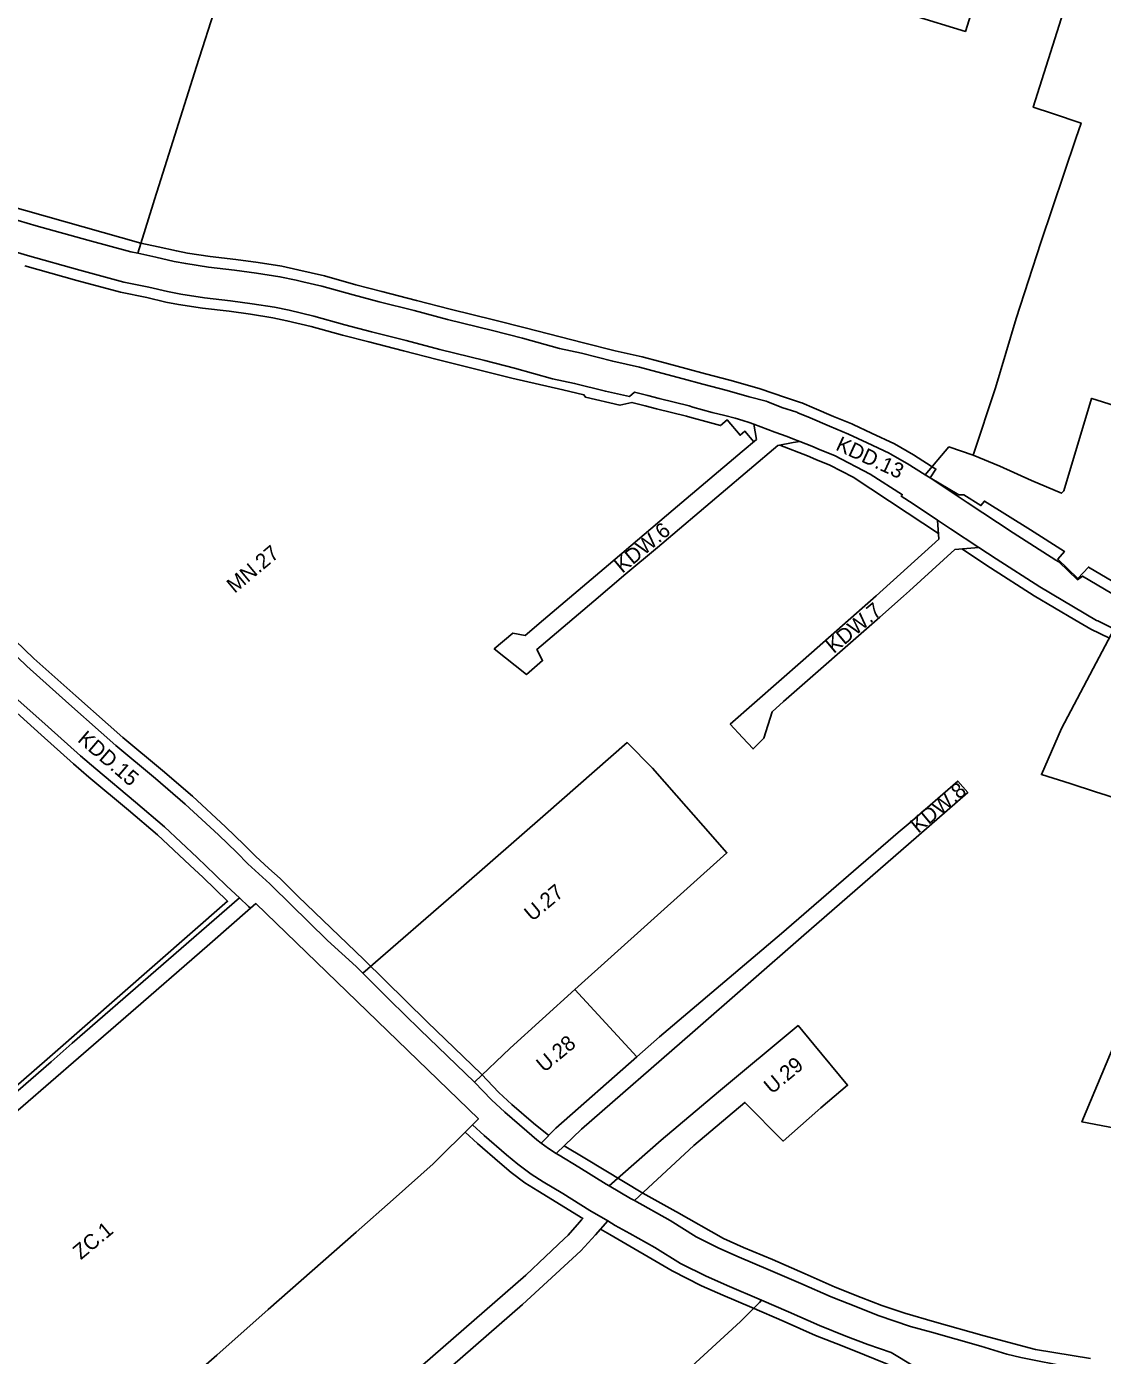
# Model space of a CAD drawing. Extents: x 7418616 to 7420822, y 5550745 to 5553106.
# Drawn here: x 7419553.4 to 7419907.9, y 5551619.2 to 5552057.3 of the extents above; entities that cross this region are included whole.
import ezdxf

# ---------------------------------------------------------------- set-up
doc = ezdxf.new("R2010")
doc.units = 0
for name, color, linetype in [('linie rozgraniczające', 7, 'Continuous'), ('nieprzekraczalne linie zabudowy', 7, 'Continuous'), ('przeznaczenia terenów', 7, 'Continuous')]:
    doc.layers.add(name, color=color, linetype=linetype)

msp = doc.modelspace()

# ---------------------------------------------------------------- linework, layer by layer
at = {"layer": 'linie rozgraniczające'}
msp.add_line((7419754.51, 5551717.59), (7419734.1, 5551739.77), dxfattribs=at)
for points in [[(7419590.08, 5551982.51), (7419596.14, 5552002.03), (7419596.33, 5552002.64), (7419609.38, 5552044.09), (7419616.1, 5552064.94), (7419622.82, 5552085.79), (7419623.46, 5552087.79), (7419628.52, 5552102.73), (7419640.17, 5552137.15), (7419652.24, 5552174.78), (7419656.71, 5552188.48), (7419662.12, 5552208.47), (7419665.26, 5552226.21)], [(7419899.38, 5552075.86), (7419885.13, 5552030.65), (7419891.5, 5552028.56), (7419900.9, 5552025.46), (7419899.21, 5552020.34), (7419887.64, 5551986.11), (7419879.49, 5551961.07), (7419872.72, 5551938.17), (7419865.35, 5551916.02)], [(7419845.58, 5552060.93), (7419862.79, 5552055.65), (7419865.66, 5552064.73)], [(7419865.35, 5551916.02), (7419874.19, 5551912.4), (7419884.62, 5551907.67), (7419894.5, 5551903.44), (7419895.18, 5551904.22), (7419904.32, 5551934.63), (7419904.45, 5551934.6), (7419911.78, 5551932.3), (7419966.62, 5551913.81), (7419997.01, 5551903.55), (7420002.31, 5551919.81), (7420018.98, 5551914.74), (7420020.36, 5551928.71), (7420011.68, 5551931.3), (7420014.17, 5551942.65), (7420015.1, 5551946.85), (7420016.72, 5551954.2), (7420042.11, 5552041.51), (7420042.23, 5552042.46), (7420042.7, 5552046.08), (7420043.73, 5552061.39)], [(7419489.5, 5552027.77), (7419490.15, 5552021.57), (7419500.93, 5552014.06), (7419527.68, 5552000.16), (7419538.61, 5551996.88), (7419556.58, 5551991.54), (7419573.63, 5551986.81), (7419587.72, 5551983.01), (7419590.08, 5551982.51)], [(7419793.1, 5551926.14), (7419791.55, 5551926.72), (7419789.46, 5551927.42), (7419786.9, 5551928.18), (7419783.52, 5551929.01), (7419779.38, 5551930.07), (7419772.98, 5551931.84), (7419771.74, 5551932.2), (7419761.85, 5551934.66), (7419758.1, 5551935.65), (7419753.76, 5551936.74), (7419752.12, 5551935.26), (7419744.18, 5551937.05), (7419734, 5551939.6), (7419726.77, 5551941.16), (7419714.24, 5551944.69), (7419704.44, 5551947.16), (7419689.64, 5551950.86), (7419678.54, 5551953.73), (7419674.58, 5551954.73), (7419667.07, 5551956.67), (7419658.32, 5551958.95), (7419648.08, 5551961.79), (7419639.94, 5551963.72), (7419635.15, 5551964.73), (7419627.72, 5551965.91), (7419620.59, 5551966.88), (7419612.04, 5551967.86), (7419604.22, 5551969.08), (7419599.86, 5551969.91), (7419593.73, 5551971.33), (7419585.49, 5551973.05), (7419570.94, 5551976.98), (7419553.71, 5551981.75), (7419530.83, 5551988.56)], [(7419590.08, 5551982.51), (7419595.98, 5551981.28), (7419602.06, 5551979.87), (7419605.88, 5551979.15), (7419613.39, 5551977.97), (7419621.9, 5551976.99), (7419629.15, 5551976.01), (7419636.88, 5551974.79), (7419642.23, 5551973.66), (7419644.49, 5551973.15), (7419650.69, 5551971.66), (7419661.01, 5551968.79), (7419669.63, 5551966.54), (7419681.09, 5551963.61), (7419692.16, 5551960.74), (7419706.92, 5551957.05), (7419716.88, 5551954.54), (7419729.08, 5551951.1), (7419736.24, 5551949.55), (7419746.6, 5551946.96), (7419755.39, 5551944.97), (7419761.14, 5551943.46), (7419769.74, 5551941.12), (7419776.21, 5551939.39), (7419784.25, 5551937.27), (7419791.56, 5551935.23), (7419797.12, 5551933.73), (7419797.64, 5551933.55), (7419802.35, 5551931.72), (7419807.22, 5551930.1), (7419807.55, 5551929.97), (7419811.62, 5551928.28), (7419817.98, 5551925.51), (7419824.27, 5551922.94), (7419830.39, 5551920.07), (7419837.71, 5551916.6), (7419838.05, 5551916.42), (7419843.65, 5551913.25), (7419849.56, 5551909.49)], [(7419808.18, 5551920.5), (7419806.08, 5551920.12), (7419800.97, 5551919.19), (7419782.27, 5551903.36), (7419761.28, 5551885.58), (7419750.91, 5551876.8), (7419740.29, 5551867.82), (7419721.57, 5551851.96), (7419723.43, 5551848.23), (7419718.12, 5551843.67), (7419707.52, 5551852.09), (7419713.65, 5551857.25), (7419717.69, 5551856.54), (7419723.8, 5551861.71), (7419745.16, 5551879.81), (7419766.52, 5551897.91), (7419789.26, 5551917.18), (7419793.99, 5551921.18), (7419793.1, 5551926.14)], [(7419808.18, 5551920.5), (7419805.92, 5551921.4), (7419804.11, 5551922.16), (7419800.03, 5551923.53), (7419793.1, 5551926.14)], [(7419853.61, 5551894.58), (7419845.56, 5551899.95), (7419841.57, 5551902.48), (7419842.05, 5551902.94), (7419831.42, 5551909.76), (7419819.63, 5551915.85), (7419814.89, 5551917.75), (7419812.13, 5551918.95), (7419808.18, 5551920.5)], [(7419849.56, 5551909.49), (7419857.35, 5551918.71), (7419865.35, 5551916.02)], [(7419849.56, 5551909.49), (7419851.18, 5551908.47), (7419863.38, 5551900.33), (7419878.5, 5551890.32), (7419892.57, 5551881.34), (7419893.54, 5551880.77), (7419899.79, 5551874.9), (7419901.38, 5551876.12), (7419911, 5551870.42)], [(7419867.26, 5551885.53), (7419859.35, 5551884.84), (7419859.3, 5551884.87), (7419844.37, 5551871.24), (7419842.43, 5551869.48), (7419834.58, 5551862.62), (7419802.87, 5551834.72), (7419799.08, 5551831.4), (7419796.39, 5551822.63), (7419792.81, 5551819.13), (7419789.38, 5551822.89), (7419785.28, 5551827.28), (7419809.36, 5551848.43), (7419833.44, 5551869.57), (7419854.09, 5551888.31), (7419853.61, 5551894.58)], [(7419867.26, 5551885.53), (7419857.87, 5551891.74), (7419853.61, 5551894.58)], [(7419911.85, 5551858.76), (7419911.3, 5551858.97), (7419906.4, 5551861.31), (7419906.05, 5551861.5), (7419887.29, 5551872.61), (7419872.98, 5551881.75), (7419867.26, 5551885.53)], [(7419540.95, 5551858.38), (7419553.46, 5551846.41), (7419567.31, 5551834), (7419577.95, 5551824.53), (7419582.85, 5551820.25), (7419595.88, 5551809.39), (7419605.69, 5551800.95), (7419616.63, 5551790.83), (7419622.68, 5551784.96), (7419626.37, 5551781.27), (7419633.53, 5551774.65), (7419634.21, 5551773.99), (7419640.4, 5551767.96), (7419652.55, 5551755.99), (7419661.97, 5551747.38), (7419664.18, 5551745.21)], [(7419988.41, 5551682.49), (7419971.74, 5551683.99), (7419954.41, 5551687.23), (7419953.33, 5551687.39), (7419935.52, 5551690.42), (7419930.19, 5551691.21), (7419926.5, 5551692.07), (7419918.42, 5551693.04), (7419912.18, 5551694.12), (7419901.21, 5551696.19), (7419910.56, 5551718.7), (7419915.44, 5551730.19), (7419924.05, 5551750.44), (7419927.87, 5551749.43), (7419943.12, 5551792.61), (7419909.21, 5551803.94), (7419905.66, 5551805.01), (7419897.3, 5551807.68), (7419887.85, 5551810.69), (7419894.5, 5551825.83), (7419905.84, 5551847.52), (7419911.85, 5551858.76)], [(7419623.53, 5551770), (7419619.37, 5551773.85), (7419615.55, 5551777.67), (7419609.66, 5551783.38), (7419598.83, 5551793.4), (7419589.26, 5551801.63), (7419576.19, 5551812.52), (7419571.18, 5551816.89), (7419560.52, 5551826.38), (7419546.59, 5551838.86), (7419534.03, 5551850.88)], [(7419664.18, 5551745.21), (7419696.62, 5551773.35), (7419724.43, 5551797.6), (7419751.29, 5551821.2), (7419759.63, 5551812.81), (7419767.57, 5551803.78), (7419776.37, 5551793.78), (7419784.19, 5551784.91), (7419734.1, 5551739.77)], [(7419754.51, 5551717.59), (7419762.03, 5551724.22), (7419802.22, 5551758.29), (7419840.67, 5551791.53), (7419844.58, 5551794.91), (7419860.29, 5551808.52), (7419863.57, 5551804.75), (7419844, 5551787.7), (7419809.56, 5551757.68), (7419772.85, 5551725.69), (7419736.24, 5551693.8), (7419727.94, 5551685.79)], [(7419537.25, 5551694.98), (7419543.78, 5551700.67), (7419561.5, 5551715.99), (7419568.41, 5551722.1), (7419623.53, 5551770)], [(7419627.2, 5551766.58), (7419626.55, 5551767.21), (7419623.53, 5551770)], [(7419449.2, 5551610.35), (7419452.46, 5551613.53), (7419453.31, 5551614.36), (7419455.41, 5551616.28), (7419477.43, 5551636.49), (7419488.09, 5551645.77), (7419515.75, 5551669.86), (7419570.49, 5551717.29), (7419589.38, 5551733.67), (7419610.42, 5551751.9), (7419613.77, 5551754.84), (7419627.2, 5551766.58)], [(7419627.2, 5551766.58), (7419628.98, 5551768.14), (7419702.3, 5551697.17), (7419700.4, 5551695.24)], [(7419664.18, 5551745.21), (7419673.16, 5551736.35), (7419682.97, 5551726.66), (7419700.97, 5551709.29)], [(7419734.1, 5551739.77), (7419712.72, 5551720.51), (7419700.97, 5551709.29)], [(7419745.4, 5551675.09), (7419762.57, 5551690.15), (7419781.39, 5551706.11), (7419807.68, 5551727.91), (7419812.82, 5551721.7), (7419823.96, 5551708.27), (7419815.15, 5551700.8), (7419814.14, 5551699.94), (7419802.72, 5551689.86), (7419790.14, 5551702.59), (7419773.32, 5551688.42), (7419753.76, 5551670.21)], [(7419722.99, 5551689.2), (7419727.87, 5551694.11), (7419754.51, 5551717.59)], [(7419700.97, 5551709.29), (7419706.57, 5551703.42), (7419711, 5551699.34), (7419718.23, 5551693.09), (7419721.55, 5551690.3), (7419722.99, 5551689.2)], [(7419700.4, 5551695.24), (7419687.42, 5551682.37), (7419674.24, 5551670.63), (7419662.03, 5551659.82), (7419633.04, 5551634.29), (7419616.09, 5551619.23), (7419593.15, 5551599.18), (7419560.75, 5551570.34), (7419548.95, 5551559.84), (7419543.61, 5551555.09)], [(7419744.92, 5551663.54), (7419739.06, 5551666.99), (7419730.16, 5551672.57), (7419723.63, 5551676.47), (7419719.68, 5551678.91), (7419715.26, 5551682.27), (7419711.59, 5551685.35), (7419704.24, 5551691.7), (7419700.4, 5551695.24)], [(7419722.99, 5551689.2), (7419725.41, 5551687.36), (7419727.94, 5551685.79)], [(7419727.94, 5551685.79), (7419728.96, 5551685.16), (7419735.43, 5551681.3), (7419744.41, 5551675.68), (7419745.4, 5551675.09)], [(7419753.76, 5551670.21), (7419752.44, 5551670.95), (7419745.4, 5551675.09)], [(7419753.76, 5551670.21), (7419765.49, 5551663.66), (7419774.08, 5551658.33), (7419781.54, 5551654.6), (7419788.27, 5551651.59), (7419797.81, 5551647.54), (7419808.59, 5551642.92), (7419818.54, 5551638.49), (7419827.18, 5551635.06), (7419834.06, 5551632.36), (7419844.69, 5551628.77), (7419851.67, 5551626.9), (7419867.92, 5551622.27), (7419876.46, 5551619.65), (7419881.01, 5551618.52), (7419897.68, 5551615.16), (7419924.17, 5551608.56), (7419941, 5551604.01), (7419967.8, 5551596.87), (7419974.49, 5551594.78)], [(7419744.92, 5551663.54), (7419740.88, 5551658.92), (7419736.08, 5551653.72), (7419716.86, 5551635.99), (7419650.11, 5551577.84), (7419609.28, 5551543.07), (7419592.03, 5551528.18), (7419583.75, 5551520.75)], [(7419752.25, 5551659.37), (7419747.41, 5551662.07), (7419744.92, 5551663.54)], [(7419795.65, 5551637.37), (7419784.23, 5551642.22), (7419777.1, 5551645.41), (7419769.31, 5551649.31), (7419768.9, 5551649.54), (7419760.41, 5551654.81), (7419752.25, 5551659.37)], [(7419665.14, 5551519.73), (7419677.92, 5551531.25), (7419704.78, 5551555.54), (7419726.91, 5551575.57), (7419749.02, 5551594.5), (7419764.54, 5551608.16), (7419788.65, 5551630.4), (7419794.9, 5551636.59), (7419795.65, 5551637.37)], [(7419891.54, 5551604.31), (7419887.32, 5551605), (7419871.27, 5551607.62), (7419866.3, 5551609.14), (7419854.51, 5551612.75), (7419846.73, 5551615.13), (7419840.56, 5551618.83), (7419838.33, 5551620.16), (7419830.69, 5551622.74), (7419823.43, 5551625.57), (7419814.68, 5551629.04), (7419804.46, 5551633.59), (7419795.65, 5551637.37)]]:
    msp.add_lwpolyline(points, dxfattribs=at)
at = {"layer": 'nieprzekraczalne linie zabudowy'}
for points in [[(7419528.06, 5552003.69), (7419591.03, 5551985.84), (7419596.73, 5551984.7), (7419602.78, 5551983.3), (7419606.47, 5551982.6), (7419613.86, 5551981.44), (7419622.32, 5551980.47), (7419629.77, 5551979.46), (7419637.49, 5551978.23), (7419642.84, 5551977.11), (7419651.58, 5551975.04), (7419661.92, 5551972.17), (7419670.5, 5551969.93), (7419681.95, 5551967), (7419693.01, 5551964.14), (7419707.77, 5551960.45), (7419717.73, 5551957.94), (7419736.98, 5551952.97), (7419747.41, 5551950.37), (7419756.28, 5551948.36), (7419762.05, 5551946.84), (7419770.65, 5551944.5), (7419777.11, 5551942.77), (7419785.12, 5551940.66), (7419792.48, 5551938.61), (7419795.19, 5551937.88), (7419803.54, 5551935.01), (7419808.46, 5551933.37), (7419808.88, 5551933.21), (7419813, 5551931.5), (7419819.33, 5551928.74), (7419825.38, 5551926.28), (7419825.76, 5551926.11), (7419831.9, 5551923.23), (7419839.42, 5551919.66), (7419845.66, 5551916.12), (7419853.08, 5551911.4), (7419851.18, 5551908.47), (7419860.66, 5551902.94), (7419862.24, 5551902.89), (7419867.93, 5551899.37), (7419869.06, 5551900.81), (7419884.29, 5551891.41), (7419895.4, 5551884.25), (7419893.24, 5551881.64), (7419899.84, 5551875.3), (7419903.35, 5551879.05), (7419907.63, 5551876.48), (7419912.65, 5551873.51)], [(7419552.87, 5551978.35), (7419569.98, 5551973.6), (7419584.3, 5551969.74), (7419592.98, 5551967.91), (7419599.28, 5551966.45), (7419603.47, 5551965.66), (7419611.41, 5551964.41), (7419620.16, 5551963.4), (7419627.21, 5551962.45), (7419634.51, 5551961.29), (7419639.17, 5551960.3), (7419647.21, 5551958.4), (7419657.49, 5551955.55), (7419666.2, 5551953.28), (7419677.67, 5551950.34), (7419688.75, 5551947.47), (7419713.34, 5551941.31), (7419730.18, 5551937.51), (7419737.08, 5551935.87), (7419737.63, 5551935.04), (7419748.96, 5551932.4), (7419752.91, 5551933.34), (7419757.23, 5551932.26), (7419760.99, 5551931.27), (7419770.83, 5551928.82), (7419772.03, 5551928.47), (7419778.48, 5551926.69), (7419782.13, 5551925.75), (7419784.31, 5551927.57), (7419788.52, 5551922.53), (7419790.14, 5551923.87), (7419793.04, 5551920.37)], [(7419801.67, 5551919.32), (7419810.8, 5551915.71), (7419813.54, 5551914.52), (7419818.17, 5551912.67), (7419825.82, 5551908.71), (7419843.65, 5551897.01), (7419853.95, 5551890.15)], [(7419442.91, 5551626.23), (7419449.02, 5551619.26), (7419486.85, 5551653.22), (7419538.64, 5551698.19), (7419561.02, 5551717.57), (7419619.62, 5551768.92), (7419611.64, 5551776.75), (7419607.25, 5551780.84), (7419596.5, 5551790.79), (7419587, 5551798.95), (7419573.92, 5551809.86), (7419568.88, 5551814.26), (7419558.18, 5551823.77), (7419544.25, 5551836.26), (7419531.42, 5551848.53), (7419521.15, 5551859.26), (7419508.99, 5551871.5), (7419501.37, 5551879.21), (7419487.71, 5551892.09), (7419480.65, 5551898.41), (7419476.05, 5551902.65), (7419475.24, 5551903.38)], [(7419861.65, 5551885.04), (7419871.09, 5551878.8), (7419885.46, 5551869.63), (7419898.86, 5551861.68), (7419904.18, 5551858.56), (7419910.31, 5551855.59)], [(7419725.48, 5551691.71), (7419720.5, 5551695.76), (7419713.33, 5551701.95), (7419709.03, 5551705.92), (7419703.27, 5551711.94), (7419685.41, 5551729.16), (7419664.57, 5551749.74), (7419642.86, 5551770.45), (7419636.93, 5551776.36), (7419633.2, 5551779.72), (7419628.8, 5551783.79), (7419625.12, 5551787.47), (7419619.01, 5551793.4), (7419608.04, 5551803.55), (7419598.15, 5551812.06), (7419585.12, 5551822.91), (7419580.27, 5551827.15), (7419569.64, 5551836.6), (7419555.84, 5551848.97), (7419543.42, 5551860.86)], [(7419581.63, 5551526.48), (7419596.27, 5551539.53), (7419609.17, 5551550.99), (7419666.82, 5551601.15), (7419717.93, 5551645.65), (7419724.41, 5551651.75), (7419730.6, 5551657.61), (7419731.91, 5551658.88), (7419735.61, 5551663.08), (7419736.33, 5551663.88), (7419736.76, 5551664.29), (7419721.88, 5551673.44), (7419717.65, 5551676.06), (7419713.06, 5551679.54), (7419709.33, 5551682.67), (7419701.95, 5551689.05), (7419697.91, 5551692.77)], [(7419730.54, 5551688.3), (7419737.35, 5551684.23), (7419756.51, 5551672.68), (7419767.35, 5551666.63), (7419767.54, 5551666.51), (7419783.04, 5551657.76), (7419789.66, 5551654.8), (7419799.18, 5551650.76), (7419809.99, 5551646.13), (7419819.9, 5551641.71), (7419828.46, 5551638.32), (7419835.26, 5551635.65), (7419842.83, 5551633.1), (7419852.58, 5551630.28), (7419868.95, 5551625.62), (7419885.86, 5551621.13), (7419904.04, 5551618.18)], [(7419742.58, 5551660.86), (7419745.62, 5551659.06), (7419766.17, 5551647.08), (7419775.79, 5551642.16), (7419782.84, 5551639.01), (7419792.43, 5551634.94), (7419803.06, 5551630.39), (7419813.36, 5551625.8), (7419822.15, 5551622.31), (7419829.56, 5551619.42), (7419840.14, 5551615.11)]]:
    msp.add_lwpolyline(points, dxfattribs=at)

# ---------------------------------------------------------------- texts
at = {"layer": 'przeznaczenia terenów'}
for s, rotation, p in [('KDD.13', 335.3031, (7419819.72, 5551917.84)), ('KDW.6', 39.8439, (7419749.74, 5551876.82)), ('MN.27', 39.8439, (7419621.98, 5551870.23)), ('KDW.7', 39.8439, (7419819.42, 5551850.36)), ('KDD.15', 319.3296, (7419569.9, 5551821.78)), ('KDW.8', 39.8439, (7419847.24, 5551791.13)), ('U.27', 39.8439, (7419720.02, 5551762.05)), ('U.28', 39.8439, (7419723.99, 5551712.26)), ('U.29', 39.8439, (7419798.99, 5551705.12)), ('ZC.1', 39.8439, (7419571.28, 5551650.54))]:
    msp.add_text(s, height=5, rotation=rotation, dxfattribs=at).set_placement(p)

doc.saveas('drawing.dxf')
